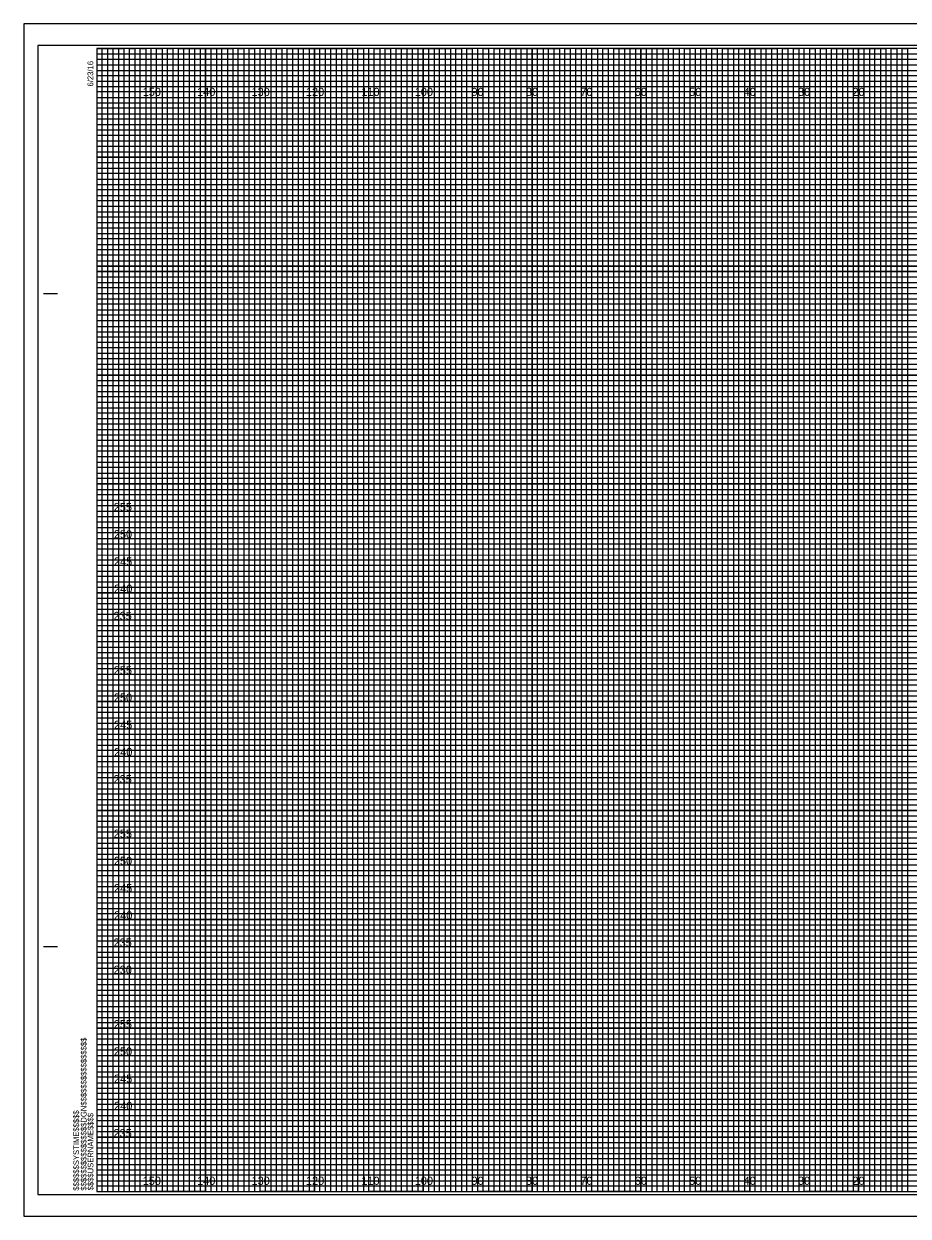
# Model space of a CAD drawing. Extents: x -13 to 323, y -5 to 434.
# Drawn here: x -13.4 to 149.1, y 215.5 to 434.5 of the extents above; entities that cross this region are included whole.
import ezdxf

# ---------------------------------------------------------------- set-up
doc = ezdxf.new("R2010")
doc.units = 0
for name, color, linetype in [('Exist Cross Section Cell', 7, 'Continuous'), ('Exist XS Center Line Elevation Label', 7, 'Continuous'), ('Exist XS Ground Line', 7, 'Continuous'), ('Prop CMT Conc Surface', 7, 'Continuous'), ('Prop CMT Concrete Structures', 7, 'Continuous'), ('Prop CMT DNC', 7, 'Continuous'), ('Prop CMT Pvmt Course 1 Wedge', 7, 'Continuous'), ('Prop CMT Pvmt Course 2', 7, 'Continuous'), ('Prop CMT Pvmt Course 2 Wedge', 7, 'Continuous'), ('Prop CMT Pvmt Course 3', 7, 'Continuous'), ('Prop CMT Subgrade Earthwork', 7, 'Continuous')]:
    doc.layers.add(name, color=color, linetype=linetype)

msp = doc.modelspace()

# ---------------------------------------------------------------- linework, layer by layer
at = {"layer": 'Exist XS Center Line Elevation Label'}
for points in [[(0, 430), (5, 430), (5, 220), (15, 220), (15, 430), (25, 430), (25, 220), (35, 220), (35, 430), (45, 430), (45, 220), (55, 220), (55, 430), (65, 430), (65, 220), (75, 220), (75, 430), (85, 430), (85, 220), (95, 220), (95, 430), (105, 430), (105, 220), (115, 220), (115, 430), (125, 430), (125, 220), (135, 220), (135, 430), (145, 430), (145, 220), (155, 220)], [(0, 425), (275, 425)], [(0, 405), (320, 405), (320, 415), (0, 415)], [(0, 385), (320, 385), (320, 395), (0, 395)], [(0, 365), (320, 365), (320, 375), (0, 375)], [(0, 345), (320, 345), (320, 355), (0, 355)], [(0, 325), (320, 325), (320, 335), (0, 335)], [(0, 305), (320, 305), (320, 315), (0, 315)], [(0, 285), (320, 285), (320, 295), (0, 295)], [(0, 265), (320, 265), (320, 275), (0, 275)], [(0, 245), (320, 245), (320, 255), (0, 255)], [(0, 225), (320, 225), (320, 235), (0, 235)]]:
    msp.add_lwpolyline(points, dxfattribs=at)
at = {"layer": 'Exist XS Ground Line'}
for p, q in [((10, 430), (0, 430)), ((10, 220), (10, 430)), ((30, 430), (20, 430)), ((20, 430), (20, 220)), ((30, 220), (30, 430)), ((50, 430), (40, 430)), ((40, 430), (40, 220)), ((50, 220), (50, 430)), ((70, 430), (60, 430)), ((60, 430), (60, 220)), ((70, 220), (70, 430)), ((90, 430), (80, 430)), ((80, 430), (80, 220)), ((90, 220), (90, 430)), ((110, 430), (100, 430)), ((100, 430), (100, 220)), ((110, 220), (110, 430)), ((130, 430), (120, 430)), ((120, 430), (120, 220)), ((130, 220), (130, 430)), ((150, 430), (140, 430)), ((140, 430), (140, 220)), ((20, 220), (10, 220)), ((40, 220), (30, 220)), ((60, 220), (50, 220)), ((80, 220), (70, 220)), ((100, 220), (90, 220)), ((120, 220), (110, 220)), ((140, 220), (130, 220))]:
    msp.add_line(p, q, dxfattribs=at)
for points in [[(0, 420), (320, 420), (320, 410), (0, 410)], [(0, 400), (320, 400), (320, 390), (0, 390)], [(0, 380), (320, 380), (320, 370), (0, 370)], [(0, 360), (320, 360), (320, 350), (0, 350)], [(0, 340), (320, 340), (320, 330), (0, 330)], [(0, 320), (320, 320), (320, 310), (0, 310)], [(0, 300), (320, 300), (320, 290), (0, 290)], [(0, 280), (320, 280), (320, 270), (0, 270)], [(0, 260), (320, 260), (320, 250), (0, 250)], [(0, 240), (320, 240), (320, 230), (0, 230)]]:
    msp.add_lwpolyline(points, dxfattribs=at)
at = {"layer": 'Prop CMT Conc Surface'}
msp.add_lwpolyline([(-13.4, 215.5), (323.3, 215.5), (323.3, 434.5), (-13.4, 434.5)], close=True, dxfattribs=at)
at = {"layer": 'Prop CMT Concrete Structures'}
for p, q in [((-9.8, 385), (-7.3, 385)), ((-9.7, 385), (-7.2, 385)), ((-9.8, 265), (-7.3, 265)), ((-9.7, 265), (-7.2, 265)), ((0, 220), (0, 220)), ((0, 220), (0, 220)), ((0, 220), (0, 220)), ((0, 220), (0, 220)), ((0, 220), (0, 220)), ((0, 220), (0, 220)), ((0, 220), (0, 220))]:
    msp.add_line(p, q, dxfattribs=at)
msp.add_lwpolyline([(320, 430), (0, 430), (0, 220), (320, 220)], close=True, dxfattribs=at)
at = {"layer": 'Prop CMT DNC'}
for points in [[(0, 220), (1, 220), (1, 430), (2, 430), (2, 220)], [(2, 220), (3, 220), (3, 430), (4, 430), (4, 220)], [(5, 220), (6, 220), (6, 430), (7, 430), (7, 220)], [(7, 220), (8, 220), (8, 430), (9, 430), (9, 220)], [(10, 220), (11, 220), (11, 430), (12, 430), (12, 220)], [(12, 220), (13, 220), (13, 430), (14, 430), (14, 220)], [(15, 220), (16, 220), (16, 430), (17, 430), (17, 220)], [(17, 220), (18, 220), (18, 430), (19, 430), (19, 220)], [(20, 220), (21, 220), (21, 430), (22, 430), (22, 220)], [(22, 220), (23, 220), (23, 430), (24, 430), (24, 220)], [(25, 220), (26, 220), (26, 430), (27, 430), (27, 220)], [(27, 220), (28, 220), (28, 430), (29, 430), (29, 220)], [(30, 220), (31, 220), (31, 430), (32, 430), (32, 220)], [(32, 220), (33, 220), (33, 430), (34, 430), (34, 220)], [(35, 220), (36, 220), (36, 430), (37, 430), (37, 220)], [(37, 220), (38, 220), (38, 430), (39, 430), (39, 220)], [(40, 220), (41, 220), (41, 430), (42, 430), (42, 220)], [(42, 220), (43, 220), (43, 430), (44, 430), (44, 220)], [(45, 220), (46, 220), (46, 430), (47, 430), (47, 220)], [(47, 220), (48, 220), (48, 430), (49, 430), (49, 220)], [(50, 220), (51, 220), (51, 430), (52, 430), (52, 220)], [(52, 220), (53, 220), (53, 430), (54, 430), (54, 220)], [(55, 220), (56, 220), (56, 430), (57, 430), (57, 220)], [(57, 220), (58, 220), (58, 430), (59, 430), (59, 220)], [(60, 220), (61, 220), (61, 430), (62, 430), (62, 220)], [(62, 220), (63, 220), (63, 430), (64, 430), (64, 220)], [(65, 220), (66, 220), (66, 430), (67, 430), (67, 220)], [(67, 220), (68, 220), (68, 430), (69, 430), (69, 220)], [(70, 220), (71, 220), (71, 430), (72, 430), (72, 220)], [(72, 220), (73, 220), (73, 430), (74, 430), (74, 220)], [(75, 220), (76, 220), (76, 430), (77, 430), (77, 220)], [(77, 220), (78, 220), (78, 430), (79, 430), (79, 220)], [(80, 220), (81, 220), (81, 430), (82, 430), (82, 220)], [(82, 220), (83, 220), (83, 430), (84, 430), (84, 220)], [(85, 220), (86, 220), (86, 430), (87, 430), (87, 220)], [(87, 220), (88, 220), (88, 430), (89, 430), (89, 220)], [(90, 220), (91, 220), (91, 430), (92, 430), (92, 220)], [(92, 220), (93, 220), (93, 430), (94, 430), (94, 220)], [(95, 220), (96, 220), (96, 430), (97, 430), (97, 220)], [(97, 220), (98, 220), (98, 430), (99, 430), (99, 220)], [(100, 220), (101, 220), (101, 430), (102, 430), (102, 220)], [(102, 220), (103, 220), (103, 430), (104, 430), (104, 220)], [(105, 220), (106, 220), (106, 430), (107, 430), (107, 220)], [(107, 220), (108, 220), (108, 430), (109, 430), (109, 220)], [(110, 220), (111, 220), (111, 430), (112, 430), (112, 220)], [(112, 220), (113, 220), (113, 430), (114, 430), (114, 220)], [(115, 220), (116, 220), (116, 430), (117, 430), (117, 220)], [(117, 220), (118, 220), (118, 430), (119, 430), (119, 220)], [(120, 220), (121, 220), (121, 430), (122, 430), (122, 220)], [(122, 220), (123, 220), (123, 430), (124, 430), (124, 220)], [(125, 220), (126, 220), (126, 430), (127, 430), (127, 220)], [(127, 220), (128, 220), (128, 430), (129, 430), (129, 220)], [(130, 220), (131, 220), (131, 430), (132, 430), (132, 220)], [(132, 220), (133, 220), (133, 430), (134, 430), (134, 220)], [(135, 220), (136, 220), (136, 430), (137, 430), (137, 220)], [(137, 220), (138, 220), (138, 430), (139, 430), (139, 220)], [(140, 220), (141, 220), (141, 430), (142, 430), (142, 220)], [(142, 220), (143, 220), (143, 430), (144, 430), (144, 220)], [(145, 220), (146, 220), (146, 430), (147, 430), (147, 220)], [(147, 220), (148, 220), (148, 430), (149, 430), (149, 220)]]:
    msp.add_lwpolyline(points, dxfattribs=at)
at = {"layer": 'Prop CMT Pvmt Course 1 Wedge'}
for p, q in [((323.3, 434.5), (-13.4, 434.5)), ((-13.4, 434.5), (-13.4, 215.5)), ((-13.4, 215.5), (323.3, 215.5))]:
    msp.add_line(p, q, dxfattribs=at)
at = {"layer": 'Prop CMT Pvmt Course 2'}
msp.add_lwpolyline([(-10.8, 219.5), (322.4, 219.5), (322.4, 430.5), (-10.8, 430.5)], close=True, dxfattribs=at)
at = {"layer": 'Prop CMT Pvmt Course 3'}
for p, q in [((10, 220), (10, 430)), ((20, 220), (20, 430)), ((30, 220), (30, 430)), ((40, 220), (40, 430)), ((50, 220), (50, 430)), ((60, 220), (60, 430)), ((70, 220), (70, 430)), ((80, 220), (80, 430)), ((90, 220), (90, 430)), ((100, 220), (100, 430)), ((110, 220), (110, 430)), ((120, 220), (120, 430)), ((130, 220), (130, 430)), ((140, 220), (140, 430)), ((0, 420), (320, 420)), ((0, 410), (320, 410)), ((0, 400), (320, 400)), ((0, 390), (320, 390)), ((0, 380), (320, 380)), ((0, 370), (320, 370)), ((0, 360), (320, 360)), ((0, 350), (320, 350)), ((0, 340), (320, 340)), ((0, 330), (320, 330)), ((0, 320), (320, 320)), ((0, 310), (320, 310)), ((0, 300), (320, 300)), ((0, 290), (320, 290)), ((0, 280), (320, 280)), ((0, 270), (320, 270)), ((0, 260), (320, 260)), ((0, 250), (320, 250)), ((0, 240), (320, 240)), ((0, 230), (320, 230))]:
    msp.add_line(p, q, dxfattribs=at)
at = {"layer": 'Prop CMT Subgrade Earthwork'}
for p, q in [((0, 429), (260, 429)), ((260, 427.98), (0, 427.98)), ((0, 427.98), (0, 427)), ((0, 427), (260, 427)), ((260, 425.89), (0, 425.89)), ((0, 425.89), (0, 424)), ((0, 424), (320, 424))]:
    msp.add_line(p, q, dxfattribs=at)
for points in [[(0, 423), (270, 423), (320, 423), (320, 422), (0, 422)], [(0, 421), (320, 421), (320, 419), (0, 419)], [(0, 418), (320, 418), (320, 417), (0, 416.98)], [(0, 416), (320, 416), (320, 414), (0, 414)], [(0, 413), (320, 413), (320, 412), (0, 412)], [(0, 411), (320, 411), (320, 409), (0, 409)], [(0, 408), (320, 408), (320, 407), (0, 407)], [(0, 406), (320, 406), (320, 404), (0, 404)], [(0, 403), (320, 403), (320, 402), (0, 402)], [(0, 401), (320, 401), (320, 399), (0, 399)], [(0, 398), (320, 398), (320, 397), (0, 397)], [(0, 396), (320, 396), (320, 393.95), (320, 393), (320, 392), (0, 392)], [(0, 394), (320, 394), (320, 393), (0, 393)], [(0, 391), (320, 391), (320, 389), (0, 389.03)], [(0, 389.03), (320, 389), (320, 388), (0, 388)], [(0, 387), (320, 387), (320, 386), (0, 386)], [(0, 384), (320, 384), (320, 383), (0, 383)], [(0, 382), (320, 382), (320, 381), (0, 381)], [(-0.07, 378.89), (320, 378.89), (320, 377.88), (-0.07, 377.88)], [(0, 377), (320, 377), (320, 376), (0, 376)], [(0, 374), (320, 374), (320, 373), (0, 373)], [(0, 372), (320, 372), (320, 371), (0, 371)], [(0, 369), (320, 369), (320, 368), (0, 368)], [(0, 367), (320, 367), (320, 366), (0, 366)], [(0, 364), (320, 364), (320, 363), (0, 363)], [(0, 362), (320, 362), (320, 361), (0, 361)], [(0, 359), (320, 359), (319.99, 357.98), (0, 358)], [(0, 357), (320, 357), (320, 356), (0, 356)], [(0, 354), (320, 354), (320, 353), (0, 353)], [(0, 352), (320, 352), (320, 351), (0, 351)], [(0, 349), (320, 349), (320, 348), (0, 348)], [(0, 347), (320, 347), (320, 346), (0, 346)], [(0, 344), (320, 344), (320, 343), (0, 343)], [(0, 342), (320, 342), (320, 341), (0, 341)], [(0, 339), (320, 339), (320, 338), (0, 338)], [(0, 336.99), (320.07, 336.91), (320, 336), (0, 336)], [(0, 334), (320, 334), (320, 333), (0, 333)], [(0, 332), (320, 332), (320, 331), (0, 331)], [(0, 329), (320, 329), (320, 328), (0, 328)], [(0, 327), (320, 327), (320, 326), (0, 326)], [(0, 324), (320, 324), (320, 323), (0, 323)], [(0, 322), (320, 322), (320, 321), (0, 321)], [(0, 319), (320, 319), (320, 318), (0, 318)], [(0, 317), (320, 317), (320, 316), (0, 316)], [(0, 314), (320, 314), (320, 313), (0, 313)], [(0, 312), (320, 312), (320, 311), (0, 311)], [(0, 309), (320, 309), (320, 308), (0, 308)], [(0, 307), (320, 307), (320, 306), (0, 306)], [(0, 304), (320, 304), (320, 303), (0, 303)], [(0, 302), (320, 302), (320, 301), (0, 301)], [(0, 299), (320, 299), (319.99, 297.98), (0, 298)], [(0, 297), (320, 297), (320, 296), (0, 296)], [(0, 294), (320, 294), (320, 293), (0, 293)], [(0, 292), (320, 292), (320, 291), (0, 291)], [(0, 289), (320, 289), (320, 288), (0, 288)], [(0, 287), (320, 287), (320, 286), (0, 286)], [(0, 284), (320, 284), (320, 283), (0, 283)], [(0, 282), (320, 282), (320, 281), (0, 281)], [(0, 279), (320, 279), (320, 278), (0, 278)], [(0, 276.99), (320.07, 276.91), (320, 276), (0, 276)], [(0, 274), (320, 274), (320, 273), (0, 273)], [(0, 272), (320, 272), (320, 271), (0, 271)], [(0, 269), (320, 269), (320, 268), (0, 268)], [(0, 267), (320, 267), (320, 266), (0, 266)], [(0, 264), (320, 264), (320, 263), (0, 263)], [(0, 262), (320, 262), (320, 261), (0, 261)], [(0, 259), (320, 259), (320, 258), (0, 258)], [(0, 257), (320, 257), (320, 256), (0, 256)], [(0, 254), (320, 254), (320, 253), (0, 253)], [(0, 252), (320, 252), (320, 251), (0, 251)], [(0, 249), (320, 249), (320, 248), (0, 248)], [(0, 247), (320, 247), (320, 246), (0, 246)], [(0, 244), (320, 244), (320, 243), (0, 243)], [(0, 242), (320, 242), (320, 241), (0, 241)], [(0, 239), (320, 239), (320, 238), (0, 238)], [(0, 237), (320, 237), (320, 236), (0, 236)], [(0, 234), (320, 234), (320, 233), (0, 233)], [(0, 232), (320, 232), (320, 231), (0, 231)], [(0, 229), (320, 229), (320, 228), (0, 228)], [(0, 227), (320, 227), (320, 226), (0, 226)], [(0, 224), (320, 224), (320, 223), (0, 223)], [(0, 222), (320, 222), (320, 221), (0, 221)]]:
    msp.add_lwpolyline(points, dxfattribs=at)

# ---------------------------------------------------------------- texts
at = {"layer": 'Exist Cross Section Cell'}
for s, p in [('150', (8.44, 421.25)), ('140', (18.44, 421.25)), ('130', (28.44, 421.25)), ('120', (38.44, 421.25)), ('110', (48.62, 421.25)), ('100', (58.44, 421.25)), ('90', (68.86, 421.25)), ('80', (78.86, 421.25)), ('70', (88.86, 421.25)), ('60', (98.86, 421.25)), ('50', (108.86, 421.25)), ('40', (118.86, 421.25)), ('30', (128.86, 421.25)), ('20', (138.86, 421.25)), ('150', (8.44, 221.25)), ('140', (18.44, 221.25)), ('130', (28.44, 221.25)), ('120', (38.44, 221.25)), ('110', (48.62, 221.25)), ('100', (58.44, 221.25)), ('90', (68.86, 221.25)), ('80', (78.86, 221.25)), ('70', (88.86, 221.25)), ('60', (98.86, 221.25)), ('50', (108.86, 221.25)), ('40', (118.86, 221.25)), ('30', (128.86, 221.25)), ('20', (138.86, 221.25))]:
    msp.add_text(s, height=1.5, dxfattribs=at).set_placement(p)
at = {"layer": 'Prop CMT Concrete Structures'}
for s, p in [('6/23/16', (-0.65, 423)), ('$$$$$$$$$$$$$$$$DGN$$$$$$$$$$$$$$$$', (-1.88, 220.18)), ('$$$$$$SYSTIME$$$$$', (-3.26, 220.18)), ('$$$$USERNAME$$$$', (-0.62, 220.23))]:
    msp.add_text(s, height=1.05, rotation=90, dxfattribs=at).set_placement(p)
at = {"layer": 'Prop CMT Pvmt Course 2 Wedge'}
for s, p in [('255', (3.13, 345)), ('250', (3.15, 340)), ('245', (3.18, 335)), ('240', (3.19, 330)), ('235', (3.09, 325)), ('255', (3.13, 315)), ('250', (3.15, 310)), ('245', (3.18, 305)), ('240', (3.19, 300)), ('235', (3.09, 295)), ('255', (3.13, 285)), ('250', (3.15, 280)), ('245', (3.18, 275)), ('240', (3.19, 270)), ('235', (3.09, 265)), ('230', (3.11, 260)), ('255', (3.13, 250)), ('250', (3.15, 245)), ('245', (3.18, 240)), ('240', (3.19, 235)), ('235', (3.09, 230))]:
    msp.add_text(s, height=1.5, dxfattribs=at).set_placement(p)

doc.saveas('drawing.dxf')
